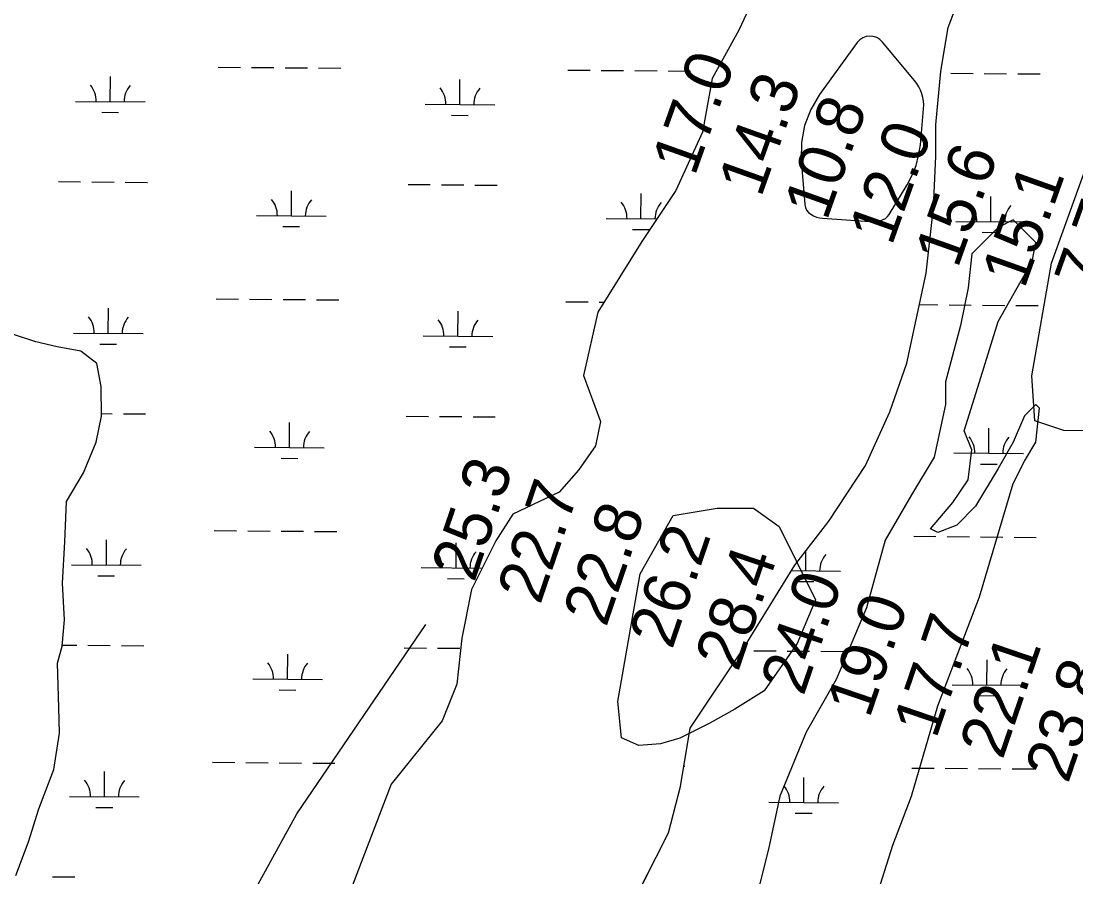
# Model space of a CAD drawing. Extents: x 3271442 to 3309282, y 752266 to 777610.
# Drawn here: x 3288161 to 3289675, y 771159 to 772387 of the extents above; entities that cross this region are included whole.
import ezdxf

# ---------------------------------------------------------------- set-up
doc = ezdxf.new("R2010")
doc.units = 0
for name, color, linetype in [('V-RIVR-RANG', 7, 'Continuous'), ('V-SITE-VEGE', 7, 'Continuous'), ('V-TOPO-DPTH', 7, 'Continuous'), ('V-TOPO-MINR', 7, 'Continuous'), ('V-WETL-SWMP', 7, 'Continuous')]:
    doc.layers.add(name, color=color, linetype=linetype)

msp = doc.modelspace()

# ---------------------------------------------------------------- linework, layer by layer
at = {"layer": 'V-SITE-VEGE'}
for points in [[(3288133.6, 769633), (3288189.4, 769695.9), (3288287.1, 769790.2), (3288391.9, 769898.4), (3288440.7, 770024.2), (3288650.1, 770425.8), (3288901.4, 770851.9), (3289072.5, 771187.1), (3289089.9, 771222), (3289107.4, 771288.4), (3289121.3, 771372.2), (3289198.1, 771487.5), (3289271.4, 771606.2), (3289320.3, 771669.1), (3289372.6, 771749.4), (3289407.5, 771826.2), (3289432, 771896.1), (3289459.9, 772025.3), (3289470.4, 772119.6), (3289473.8, 772192.9), (3289473.8, 772238.3), (3289480.8, 772315.2), (3289491.3, 772378), (3289519.2, 772451.3)], [(3289611.9, 772042.3), (3289617.3, 772069.4), (3289606.5, 772080.2), (3289584.9, 772101.8), (3289563.2, 772091), (3289547, 772074.8), (3289525.4, 772053.1), (3289520, 772004.5), (3289509.2, 771950.4), (3289487.5, 771869.2), (3289487.5, 771836.8), (3289471.3, 771761.1), (3289438.9, 771707), (3289401, 771642.1), (3289374, 771544.7), (3289330.7, 771442), (3289287.5, 771366.2), (3289249.6, 771274.3), (3289233.4, 771198.6), (3289217.2, 771133.7)], [(3289379.4, 771101.2), (3289411.8, 771204), (3289438.9, 771274.3), (3289476.7, 771404.1), (3289536.2, 771560.9), (3289584.9, 771723.2), (3289601.1, 771755.7), (3289617.3, 771782.7), (3289622.7, 771831.4), (3289617.3, 771836.8), (3289601.1, 771820.6), (3289584.9, 771782.7), (3289563.2, 771744.8), (3289530.8, 771690.8), (3289503.8, 771663.7), (3289476.7, 771652.9), (3289465.9, 771658.3), (3289498.3, 771696.2), (3289520, 771728.6), (3289525.4, 771771.9), (3289514.6, 771798.9), (3289536.2, 771869.2), (3289563.2, 771955.8), (3289590.3, 772004.5), (3289611.9, 772042.3)]]:
    msp.add_lwpolyline(points, dxfattribs=at)
at = {"layer": 'V-TOPO-DPTH'}
for points in [[(3289288.1, 772115.9), (3289290.8, 772112.7), (3289294.1, 772109.9), (3289298.1, 772107.7), (3289302.3, 772106), (3289306.7, 772104.9), (3289311.2, 772104.3), (3289378.9, 772099.6), (3289382.9, 772099.5), (3289386.9, 772099.7), (3289390.8, 772100.2), (3289394.7, 772100.9), (3289398.3, 772102.3), (3289401.5, 772104.1), (3289404.3, 772106.6), (3289406.6, 772109.7), (3289432.6, 772152.4), (3289439.6, 772165.9), (3289445.3, 772179.9), (3289449, 772194.4), (3289451.5, 772209.5), (3289456.2, 772261.5), (3289456.4, 772267), (3289456.1, 772272.4), (3289455.1, 772277.8), (3289453.8, 772283.1), (3289451.8, 772288.2), (3289449.4, 772293.1), (3289446.5, 772297.7), (3289443.2, 772302.1), (3289397, 772357.3), (3289393.1, 772360.9), (3289388.8, 772363.6), (3289383.9, 772365.1), (3289378.7, 772365.8), (3289373.5, 772365), (3289368.7, 772363.3), (3289364.6, 772360.4), (3289360.9, 772356.7), (3289306.8, 772282.1), (3289294.2, 772260.2), (3289285.1, 772237.3), (3289281, 772213), (3289280.3, 772187.7), (3289285.5, 772124), (3289286.5, 772119.8), (3289288.1, 772115.9)], [(3289703.6, 771799.2), (3289657.4, 771799.3), (3289615.8, 771813.3), (3289611.3, 771878.1), (3289639.5, 772039.8), (3289704.6, 772220)]]:
    msp.add_lwpolyline(points, dxfattribs=at)
at = {"layer": 'V-TOPO-MINR'}
for points in [[(3289288.1, 772115.9), (3289290.8, 772112.7), (3289294.1, 772109.9), (3289298.1, 772107.7), (3289302.3, 772106), (3289306.7, 772104.9), (3289311.2, 772104.3), (3289378.9, 772099.6), (3289382.9, 772099.5), (3289386.9, 772099.7), (3289390.8, 772100.2), (3289394.7, 772100.9), (3289398.3, 772102.3), (3289401.5, 772104.1), (3289404.3, 772106.6), (3289406.6, 772109.7), (3289432.6, 772152.4), (3289439.6, 772165.9), (3289445.3, 772179.9), (3289449, 772194.4), (3289451.5, 772209.5), (3289456.2, 772261.5), (3289456.4, 772267), (3289456.1, 772272.4), (3289455.1, 772277.8), (3289453.8, 772283.1), (3289451.8, 772288.2), (3289449.4, 772293.1), (3289446.5, 772297.7), (3289443.2, 772302.1), (3289397, 772357.3), (3289393.1, 772360.9), (3289388.8, 772363.6), (3289383.9, 772365.1), (3289378.7, 772365.8), (3289373.5, 772365), (3289368.7, 772363.3), (3289364.6, 772360.4), (3289360.9, 772356.7), (3289306.8, 772282.1), (3289294.2, 772260.2), (3289285.1, 772237.3), (3289281, 772213), (3289280.3, 772187.7), (3289285.5, 772124), (3289286.5, 772119.8), (3289288.1, 772115.9)], [(3287844.8, 768505.2), (3287945.7, 768641.1), (3288047.6, 768731.8), (3288186.8, 768817), (3288288.6, 768880.9), (3288336.9, 768961), (3288369.3, 769078.5), (3288369.7, 769249.7), (3288364.8, 769436.8), (3288317.2, 769634.8), (3288285.3, 769736.5), (3288285.8, 769912.9), (3288318.6, 770223), (3288329.8, 770404.8), (3288357.2, 770666.7), (3288368.3, 770853.9), (3288427.5, 771014.1), (3288556.4, 771249.1), (3288741.7, 771521.2)]]:
    msp.add_lwpolyline(points, dxfattribs=at)
for points in [[(3289611.3, 771878.1), (3289639.5, 772039.8), (3289704.6, 772220), (3289769.4, 772256.8), (3289861.9, 772256.6), (3289917.3, 772237.9), (3289991.2, 772186.9), (3290069.7, 772131.2), (3290125, 772094.1), (3290235.8, 772015.2), (3290305, 771954.9), (3290309.5, 771899.4), (3290309.5, 771880.9), (3290304.8, 771853.2), (3290267.7, 771811.7), (3290226.1, 771811.8), (3290105.9, 771812.1), (3290018, 771812.3), (3289888.5, 771803.4), (3289777.6, 771799), (3289703.6, 771799.2), (3289657.4, 771799.3), (3289615.8, 771813.3)], [(3289017.4, 771410.4), (3289049.3, 771593.9), (3289096.7, 771677.7), (3289159.7, 771688), (3289212.2, 771687.9), (3289248.8, 771661.6), (3289301, 771556.6), (3289274.6, 771493.7), (3289227.2, 771425.6), (3289185.2, 771399.5), (3289148.5, 771378.6), (3289106.4, 771357.8), (3289078.6, 771349.4), (3289047.6, 771347), (3289022.5, 771358)]]:
    msp.add_lwpolyline(points, close=True, dxfattribs=at)
at = {"layer": 'V-WETL-SWMP'}
for p, q in [((3289491.3, 772378), (3289519.2, 772451.3)), ((3289215.6, 772426.9), (3289191.1, 772374.5)), ((3289191.1, 772374.5), (3289152.7, 772304.7)), ((3289480.8, 772315.1), (3289491.3, 772378)), ((3288443.6, 772321.2), (3288475.6, 772320.9)), ((3288491.6, 772320.8), (3288523.6, 772320.5)), ((3288539.6, 772320.4), (3288571.6, 772320.1)), ((3288587.6, 772320), (3288619.6, 772319.7)), ((3288288.6, 772271.7), (3288288.9, 772307.7)), ((3288945.5, 772317), (3288977.5, 772316.8)), ((3288993.5, 772316.6), (3289025.5, 772316.4)), ((3289041.5, 772316.2), (3289073.5, 772316)), ((3289089.5, 772315.8), (3289121.5, 772315.6)), ((3289152.7, 772304.7), (3289138.8, 772227.8)), ((3289473.8, 772238.3), (3289480.8, 772315.1)), ((3289495.3, 772312.5), (3289527.3, 772312.2)), ((3289543.3, 772312.1), (3289575.3, 772311.8)), ((3289591.3, 772311.7), (3289623.3, 772311.4)), ((3288790.5, 772267.6), (3288790.7, 772303.6)), ((3288238.6, 772272.1), (3288338.6, 772271.3)), ((3288740.5, 772268), (3288840.5, 772267.2)), ((3288276.4, 772256.4), (3288300.4, 772256.2)), ((3288778.3, 772252.2), (3288802.3, 772252)), ((3289473.8, 772192.9), (3289473.8, 772238.3)), ((3289138.8, 772227.8), (3289100.4, 772144)), ((3289470.4, 772119.6), (3289473.8, 772192.9)), ((3288214.2, 772156.9), (3288246.2, 772156.6)), ((3288262.2, 772156.5), (3288294.2, 772156.2)), ((3288310.2, 772156.1), (3288342.2, 772155.8)), ((3288548.7, 772107.7), (3288549, 772143.7)), ((3288716.1, 772152.7), (3288748.1, 772152.5)), ((3288764.1, 772152.3), (3288796.1, 772152.1)), ((3288812.1, 772151.9), (3288844.1, 772151.7)), ((3289050.5, 772103.6), (3289050.8, 772139.6)), ((3289100.4, 772144), (3289051.5, 772070.7)), ((3289552.4, 772099.4), (3289552.7, 772135.4)), ((3288498.7, 772108.1), (3288598.7, 772107.3)), ((3289459.9, 772025.3), (3289470.4, 772119.6)), ((3289000.5, 772104), (3289073.3, 772103.4)), ((3289502.4, 772099.8), (3289602.4, 772099)), ((3288536.5, 772092.4), (3288560.5, 772092.2)), ((3289038.4, 772088.2), (3289062.4, 772088)), ((3289540.3, 772084.1), (3289564.3, 772083.9)), ((3289051.5, 772070.7), (3288988.7, 771969.4)), ((3289432, 771896.1), (3289459.9, 772025.3)), ((3288440.8, 771988.5), (3288472.8, 771988.2)), ((3288488.8, 771988.1), (3288520.8, 771987.8)), ((3288536.8, 771987.7), (3288568.8, 771987.4)), ((3288584.8, 771987.3), (3288616.8, 771987.1)), ((3288285.8, 771939), (3288286.1, 771975)), ((3288942.7, 771984.4), (3288974.7, 771984.1)), ((3288990.7, 771984), (3288997.7, 771983.9)), ((3289450.1, 771980.2), (3289476.6, 771980)), ((3289492.6, 771979.8), (3289524.6, 771979.6)), ((3289540.6, 771979.4), (3289572.6, 771979.2)), ((3289588.6, 771979), (3289620.6, 771978.8)), ((3288787.7, 771934.9), (3288788, 771970.9)), ((3288988.7, 771969.4), (3288967.8, 771878.6)), ((3288181.7, 771927), (3288147.2, 771938.2)), ((3288212.7, 771919.8), (3288181.7, 771927)), ((3288235.8, 771939.4), (3288335.8, 771938.6)), ((3288737.7, 771935.3), (3288837.7, 771934.5)), ((3288246.7, 771913.3), (3288212.7, 771919.8)), ((3288269.5, 771895.6), (3288246.7, 771913.3)), ((3288273.7, 771923.7), (3288297.7, 771923.5)), ((3288775.6, 771919.6), (3288799.6, 771919.4)), ((3289407.5, 771826.2), (3289432, 771896.1)), ((3288275.8, 771862.8), (3288269.5, 771895.6)), ((3288967.8, 771878.6), (3288992.2, 771812.2)), ((3288276.2, 771820), (3288275.8, 771862.8)), ((3288268.4, 771782.6), (3288276.2, 771820)), ((3288276.2, 771823.7), (3288291.5, 771823.6)), ((3288307.5, 771823.4), (3288339.5, 771823.2)), ((3288713.4, 771820.1), (3288745.4, 771819.8)), ((3289372.6, 771749.4), (3289407.5, 771826.2)), ((3288545.9, 771775), (3288546.2, 771811)), ((3288761.4, 771819.7), (3288793.4, 771819.4)), ((3288809.4, 771819.3), (3288841.4, 771819)), ((3288992.2, 771812.2), (3288985.2, 771777.3)), ((3289549.7, 771766.8), (3289550, 771802.8)), ((3288250.1, 771738.7), (3288268.4, 771782.6)), ((3288495.9, 771775.4), (3288595.9, 771774.6)), ((3288985.2, 771777.3), (3288960.8, 771742.4)), ((3288533.8, 771759.7), (3288557.8, 771759.5)), ((3289499.7, 771767.2), (3289599.7, 771766.3)), ((3289320.3, 771669.1), (3289372.6, 771749.4)), ((3289537.6, 771751.4), (3289561.6, 771751.2)), ((3288225.9, 771697.8), (3288250.1, 771738.7)), ((3288960.8, 771742.4), (3288932.9, 771711)), ((3288932.9, 771711), (3288866.5, 771679.5)), ((3288223.4, 771639.8), (3288225.9, 771697.8)), ((3288866.5, 771679.5), (3288842.1, 771641.1)), ((3289271.4, 771606.2), (3289320.3, 771669.1)), ((3288438.1, 771655.8), (3288470.1, 771655.6)), ((3288486.1, 771655.4), (3288518.1, 771655.2)), ((3288534.1, 771655), (3288566.1, 771654.8)), ((3288582.1, 771654.7), (3288614.1, 771654.4)), ((3288220.2, 771580.1), (3288223.4, 771639.8)), ((3288283.1, 771606.4), (3288283.4, 771642.4)), ((3288842.1, 771641.1), (3288807.2, 771571.3)), ((3289441.9, 771647.6), (3289473.9, 771647.3)), ((3289489.9, 771647.2), (3289521.9, 771646.9)), ((3289537.9, 771646.8), (3289569.9, 771646.5)), ((3289585.9, 771646.4), (3289617.9, 771646.1)), ((3288785, 771602.2), (3288785.3, 771638.2)), ((3289286.9, 771598.1), (3289287.1, 771626.4)), ((3288233.1, 771606.8), (3288333.1, 771606)), ((3288735, 771602.6), (3288822.5, 771601.9)), ((3289198.1, 771487.5), (3289271.4, 771606.2)), ((3289266.5, 771598.3), (3289336.9, 771597.7)), ((3288223, 771527.9), (3288220.2, 771580.1)), ((3288271, 771591), (3288295, 771590.8)), ((3288772.8, 771586.9), (3288796.8, 771586.7)), ((3289274.7, 771582.8), (3289298.7, 771582.6)), ((3288807.2, 771571.3), (3288793.2, 771501.4)), ((3288219.9, 771489.9), (3288223, 771527.9)), ((3288212.8, 771465.3), (3288219.9, 771489.9)), ((3288220, 771491.5), (3288240.7, 771491.3)), ((3288256.7, 771491.2), (3288288.7, 771490.9)), ((3288304.7, 771490.8), (3288336.7, 771490.5)), ((3288710.6, 771487.4), (3288742.6, 771487.1)), ((3288758.6, 771487), (3288790.6, 771486.8)), ((3288793.2, 771501.4), (3288786.3, 771435.1)), ((3289121.3, 771372.2), (3289198.1, 771487.5)), ((3288543.2, 771442.4), (3288543.5, 771478.4)), ((3289212.5, 771483.3), (3289244.5, 771483)), ((3289260.5, 771482.9), (3289292.5, 771482.6)), ((3289308.5, 771482.5), (3289340.5, 771482.2)), ((3288214.9, 771402), (3288212.8, 771465.3)), ((3289547, 771434.1), (3289547.3, 771470.1)), ((3288493.2, 771442.8), (3288593.2, 771441.9)), ((3288531, 771427), (3288555, 771426.8)), ((3288786.3, 771435.1), (3288765.3, 771382.7)), ((3289497, 771434.5), (3289597, 771433.7)), ((3289534.8, 771418.8), (3289558.8, 771418.6)), ((3288215.9, 771365.1), (3288214.9, 771402)), ((3288765.3, 771382.7), (3288692, 771291.9)), ((3289107.4, 771288.4), (3289121.3, 771372.2)), ((3288207.5, 771313), (3288215.9, 771365.1)), ((3288435.3, 771323.2), (3288467.3, 771322.9)), ((3288483.3, 771322.8), (3288515.3, 771322.5)), ((3288531.3, 771322.4), (3288563.3, 771322.1)), ((3288579.3, 771322), (3288611.3, 771321.7)), ((3288186.2, 771256.3), (3288207.5, 771313)), ((3288280.3, 771273.7), (3288280.6, 771309.7)), ((3289112.2, 771317.6), (3289113.2, 771317.6)), ((3289439.1, 771314.9), (3289471.1, 771314.6)), ((3289487.1, 771314.5), (3289519.1, 771314.2)), ((3289535.1, 771314.1), (3289567.1, 771313.9)), ((3289583.1, 771313.7), (3289615.1, 771313.5)), ((3288692, 771291.9), (3288569.9, 770974.1)), ((3289284.1, 771265.4), (3289284.4, 771301.4)), ((3289089.9, 771222), (3289107.4, 771288.4)), ((3288230.3, 771274.1), (3288330.3, 771273.3)), ((3289234.1, 771265.9), (3289334.1, 771265)), ((3288171.4, 771208.9), (3288186.2, 771256.3)), ((3288268.2, 771258.4), (3288292.2, 771258.2)), ((3289272, 771250.1), (3289296, 771249.9)), ((3289072.5, 771187.1), (3289089.9, 771222)), ((3288153, 771160.4), (3288171.4, 771208.9)), ((3288901.4, 770851.9), (3289072.5, 771187.1)), ((3288206, 771158.9), (3288238, 771158.6))]:
    msp.add_line(p, q, dxfattribs=at)
for centre, start, end in [((3288233.3, 772272.6), 358.7563, 40.2999), ((3288343.8, 772271.7), 138.7563, 180.2999), ((3288735.2, 772268.5), 358.7563, 40.2999), ((3288845.7, 772267.6), 138.7563, 180.2999), ((3288493.4, 772108.6), 358.7563, 40.2999), ((3288603.9, 772107.7), 138.7563, 180.2999), ((3288995.3, 772104.5), 358.7563, 40.2999), ((3289105.8, 772103.6), 138.7563, 180.2999), ((3289497.2, 772100.3), 358.7563, 40.2999), ((3289607.7, 772099.4), 138.7563, 180.2999), ((3288230.6, 771940), 358.7563, 40.2999), ((3288341.1, 771939.1), 138.7563, 180.2999), ((3288732.5, 771935.8), 358.7563, 40.2999), ((3288843, 771934.9), 138.7563, 180.2999), ((3288490.7, 771776), 358.7563, 40.2999), ((3288601.2, 771775), 138.7563, 180.2999), ((3289494.5, 771767.7), 358.7563, 40.2999), ((3289604.9, 771766.8), 138.7563, 180.2999), ((3288227.8, 771607.3), 358.7563, 40.2999), ((3288338.3, 771606.4), 138.7563, 180.2999), ((3288729.7, 771603.2), 358.7563, 40.2999), ((3288840.2, 771602.3), 138.7563, 180.2999), ((3289342.1, 771598.1), 138.7563, 180.2999), ((3289231.6, 771599), 358.7563, 359.7011), ((3288487.9, 771443.3), 358.7563, 40.2999), ((3288598.4, 771442.4), 138.7563, 180.2999), ((3289491.7, 771435), 358.7563, 40.2999), ((3289602.2, 771434.1), 138.7563, 180.2999), ((3288225.1, 771274.6), 358.7563, 40.2999), ((3288335.6, 771273.7), 138.7563, 180.2999), ((3289228.9, 771266.4), 358.7563, 40.2999), ((3289339.4, 771265.5), 138.7563, 180.2999)]:
    msp.add_arc(centre, 35.2, start, end, dxfattribs=at)

# ---------------------------------------------------------------- texts
at = {"layer": 'V-RIVR-RANG'}
for s, rotation, p in [('17.0', 70.3783, (3289127.5, 772163.3)), ('14.3', 70.3783, (3289222.7, 772132.7)), ('10.8', 70.3783, (3289317, 772099.3)), ('12.0', 70.3783, (3289410.3, 772063.2)), ('15.6', 70.3783, (3289504.9, 772030.9)), ('15.1', 70.3783, (3289600.6, 772001.5)), ('7.7', 70.3783, (3289705.3, 771997.2)), ('25.3', 71.1483, (3288811, 771580.1)), ('22.7', 71.1483, (3288905.7, 771548)), ('22.8', 71.1483, (3289000.4, 771515.9)), ('26.2', 71.1483, (3289095.1, 771483.8)), ('28.4', 71.1483, (3289189.8, 771451.7)), ('24.0', 71.1483, (3289283.6, 771416.9)), ('19.0', 71.1483, (3289378.3, 771384.8)), ('17.7', 71.1483, (3289474, 771355.5)), ('22.1', 71.1483, (3289569.4, 771325.6)), ('23.8', 71.1483, (3289663.4, 771291.3))]:
    msp.add_text(s, height=67, rotation=rotation, dxfattribs=at).set_placement(p)

doc.saveas('drawing.dxf')
